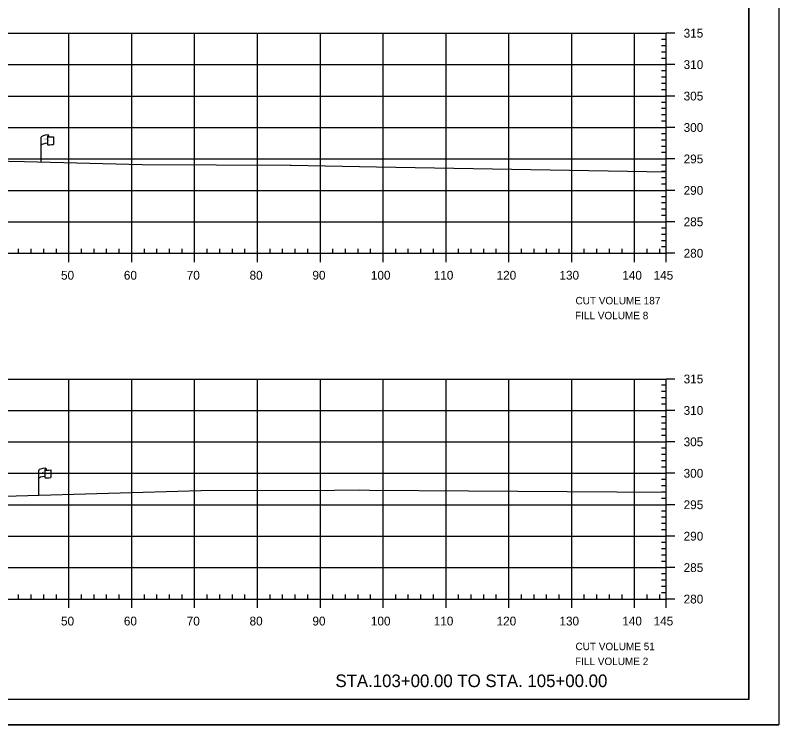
# Model space of a CAD drawing. Extents: x 1370843 to 1371177, y 380307 to 382654.
# Drawn here: x 1371055.2 to 1371176.6, y 380520.8 to 380633.6 of the extents above; entities that cross this region are included whole.
import ezdxf

# ---------------------------------------------------------------- set-up
doc = ezdxf.new("R2010")
doc.units = 0
for name, color, linetype in [('R_Axis', 7, 'Continuous'), ('R_Axis Annot', 7, 'Continuous'), ('R_Border', 7, 'Continuous'), ('R_Border Notes', 7, 'Continuous'), ('R_Draft', 7, 'Continuous'), ('R_Exist Surface', 7, 'Continuous'), ('R_Grid', 7, 'Continuous'), ('R_No Plot', 7, 'Continuous'), ('R_ROW', 7, 'Continuous')]:
    doc.layers.add(name, color=color, linetype=linetype)

msp = doc.modelspace()

# ---------------------------------------------------------------- linework, layer by layer
at = {"layer": 'R_Axis'}
for p, q in [((1371158.71, 380595.79), (1371158.71, 380630.79)), ((1371160.11, 380630.79), (1371158.71, 380630.79)), ((1371158.71, 380629.79), (1371158.01, 380629.79)), ((1371158.71, 380628.79), (1371158.01, 380628.79)), ((1371158.71, 380627.79), (1371158.01, 380627.79)), ((1371158.71, 380626.79), (1371158.01, 380626.79)), ((1371160.11, 380625.79), (1371158.71, 380625.79)), ((1371158.71, 380624.79), (1371158.01, 380624.79)), ((1371158.71, 380623.79), (1371158.01, 380623.79)), ((1371158.71, 380622.79), (1371158.01, 380622.79)), ((1371158.71, 380621.79), (1371158.01, 380621.79)), ((1371160.11, 380620.79), (1371158.71, 380620.79)), ((1371158.71, 380619.79), (1371158.01, 380619.79)), ((1371158.71, 380618.79), (1371158.01, 380618.79)), ((1371158.71, 380617.79), (1371158.01, 380617.79)), ((1371158.71, 380616.79), (1371158.01, 380616.79)), ((1371160.11, 380615.79), (1371158.71, 380615.79)), ((1371158.71, 380614.79), (1371158.01, 380614.79)), ((1371158.71, 380613.79), (1371158.01, 380613.79)), ((1371158.71, 380612.79), (1371158.01, 380612.79)), ((1371158.71, 380611.79), (1371158.01, 380611.79)), ((1371160.11, 380610.79), (1371158.71, 380610.79)), ((1371158.71, 380609.79), (1371158.01, 380609.79)), ((1371158.71, 380608.79), (1371158.01, 380608.79)), ((1371158.71, 380607.79), (1371158.01, 380607.79)), ((1371158.71, 380606.79), (1371158.01, 380606.79)), ((1371160.11, 380605.79), (1371158.71, 380605.79)), ((1371158.71, 380604.79), (1371158.01, 380604.79)), ((1371158.71, 380603.79), (1371158.01, 380603.79)), ((1371158.71, 380602.79), (1371158.01, 380602.79)), ((1371158.71, 380601.79), (1371158.01, 380601.79)), ((1371158.71, 380599.79), (1371158.01, 380599.79)), ((1371160.11, 380600.79), (1371158.71, 380600.79)), ((1371158.71, 380598.79), (1371158.01, 380598.79)), ((1371158.71, 380597.79), (1371158.01, 380597.79)), ((1371055.71, 380595.79), (1371055.71, 380596.49)), ((1371057.71, 380595.79), (1371057.71, 380596.49)), ((1371059.71, 380595.79), (1371059.71, 380596.49)), ((1371061.71, 380595.79), (1371061.71, 380596.49)), ((1371065.71, 380595.79), (1371065.71, 380596.49)), ((1371067.71, 380595.79), (1371067.71, 380596.49)), ((1371069.71, 380595.79), (1371069.71, 380596.49)), ((1371071.71, 380595.79), (1371071.71, 380596.49)), ((1371075.71, 380595.79), (1371075.71, 380596.49)), ((1371077.71, 380595.79), (1371077.71, 380596.49)), ((1371079.71, 380595.79), (1371079.71, 380596.49)), ((1371081.71, 380595.79), (1371081.71, 380596.49)), ((1371085.71, 380595.79), (1371085.71, 380596.49)), ((1371087.71, 380595.79), (1371087.71, 380596.49)), ((1371089.71, 380595.79), (1371089.71, 380596.49)), ((1371091.71, 380595.79), (1371091.71, 380596.49)), ((1371095.71, 380595.79), (1371095.71, 380596.49)), ((1371097.71, 380595.79), (1371097.71, 380596.49)), ((1371099.71, 380595.79), (1371099.71, 380596.49)), ((1371101.71, 380595.79), (1371101.71, 380596.49)), ((1371105.71, 380595.79), (1371105.71, 380596.49)), ((1371107.71, 380595.79), (1371107.71, 380596.49)), ((1371109.71, 380595.79), (1371109.71, 380596.49)), ((1371111.71, 380595.79), (1371111.71, 380596.49)), ((1371115.71, 380595.79), (1371115.71, 380596.49)), ((1371117.71, 380595.79), (1371117.71, 380596.49)), ((1371119.71, 380595.79), (1371119.71, 380596.49)), ((1371121.71, 380595.79), (1371121.71, 380596.49)), ((1371125.71, 380595.79), (1371125.71, 380596.49)), ((1371127.71, 380595.79), (1371127.71, 380596.49)), ((1371129.71, 380595.79), (1371129.71, 380596.49)), ((1371131.71, 380595.79), (1371131.71, 380596.49)), ((1371135.71, 380595.79), (1371135.71, 380596.49)), ((1371137.71, 380595.79), (1371137.71, 380596.49)), ((1371139.71, 380595.79), (1371139.71, 380596.49)), ((1371141.71, 380595.79), (1371141.71, 380596.49)), ((1371145.71, 380595.79), (1371145.71, 380596.49)), ((1371147.71, 380595.79), (1371147.71, 380596.49)), ((1371149.71, 380595.79), (1371149.71, 380596.49)), ((1371151.71, 380595.79), (1371151.71, 380596.49)), ((1371155.71, 380595.79), (1371155.71, 380596.49)), ((1371157.71, 380595.79), (1371157.71, 380596.49)), ((1371158.71, 380596.79), (1371158.01, 380596.79)), ((1370868.71, 380595.79), (1371158.71, 380595.79)), ((1371063.71, 380594.39), (1371063.71, 380595.79)), ((1371073.71, 380594.39), (1371073.71, 380595.79)), ((1371083.71, 380594.39), (1371083.71, 380595.79)), ((1371093.71, 380594.39), (1371093.71, 380595.79)), ((1371103.71, 380594.39), (1371103.71, 380595.79)), ((1371113.71, 380594.39), (1371113.71, 380595.79)), ((1371123.71, 380594.39), (1371123.71, 380595.79)), ((1371133.71, 380594.39), (1371133.71, 380595.79)), ((1371143.71, 380594.39), (1371143.71, 380595.79)), ((1371153.71, 380594.39), (1371153.71, 380595.79)), ((1371158.71, 380594.39), (1371158.71, 380595.79)), ((1371160.11, 380595.79), (1371158.71, 380595.79)), ((1371158.71, 380540.79), (1371158.71, 380575.79)), ((1371160.11, 380575.79), (1371158.71, 380575.79)), ((1371158.71, 380574.79), (1371158.01, 380574.79)), ((1371158.71, 380573.79), (1371158.01, 380573.79)), ((1371158.71, 380572.79), (1371158.01, 380572.79)), ((1371158.71, 380571.79), (1371158.01, 380571.79)), ((1371160.11, 380570.79), (1371158.71, 380570.79)), ((1371158.71, 380569.79), (1371158.01, 380569.79)), ((1371158.71, 380568.79), (1371158.01, 380568.79)), ((1371158.71, 380567.79), (1371158.01, 380567.79)), ((1371158.71, 380566.79), (1371158.01, 380566.79)), ((1371160.11, 380565.79), (1371158.71, 380565.79)), ((1371158.71, 380564.79), (1371158.01, 380564.79)), ((1371158.71, 380563.79), (1371158.01, 380563.79)), ((1371158.71, 380562.79), (1371158.01, 380562.79)), ((1371158.71, 380561.79), (1371158.01, 380561.79)), ((1371158.71, 380559.79), (1371158.01, 380559.79)), ((1371160.11, 380560.79), (1371158.71, 380560.79)), ((1371158.71, 380558.79), (1371158.01, 380558.79)), ((1371158.71, 380557.79), (1371158.01, 380557.79)), ((1371158.71, 380556.79), (1371158.01, 380556.79)), ((1371158.71, 380554.79), (1371158.01, 380554.79)), ((1371160.11, 380555.79), (1371158.71, 380555.79)), ((1371158.71, 380553.79), (1371158.01, 380553.79)), ((1371158.71, 380552.79), (1371158.01, 380552.79)), ((1371158.71, 380551.79), (1371158.01, 380551.79)), ((1371160.11, 380550.79), (1371158.71, 380550.79)), ((1371158.71, 380549.79), (1371158.01, 380549.79)), ((1371158.71, 380548.79), (1371158.01, 380548.79)), ((1371158.71, 380547.79), (1371158.01, 380547.79)), ((1371158.71, 380546.79), (1371158.01, 380546.79)), ((1371160.11, 380545.79), (1371158.71, 380545.79)), ((1371158.71, 380544.79), (1371158.01, 380544.79)), ((1371158.71, 380543.79), (1371158.01, 380543.79)), ((1371158.71, 380542.79), (1371158.01, 380542.79)), ((1371055.71, 380540.79), (1371055.71, 380541.49)), ((1371057.71, 380540.79), (1371057.71, 380541.49)), ((1371059.71, 380540.79), (1371059.71, 380541.49)), ((1371061.71, 380540.79), (1371061.71, 380541.49)), ((1371065.71, 380540.79), (1371065.71, 380541.49)), ((1371067.71, 380540.79), (1371067.71, 380541.49)), ((1371069.71, 380540.79), (1371069.71, 380541.49)), ((1371071.71, 380540.79), (1371071.71, 380541.49)), ((1371075.71, 380540.79), (1371075.71, 380541.49)), ((1371077.71, 380540.79), (1371077.71, 380541.49)), ((1371079.71, 380540.79), (1371079.71, 380541.49)), ((1371081.71, 380540.79), (1371081.71, 380541.49)), ((1371085.71, 380540.79), (1371085.71, 380541.49)), ((1371087.71, 380540.79), (1371087.71, 380541.49)), ((1371089.71, 380540.79), (1371089.71, 380541.49)), ((1371091.71, 380540.79), (1371091.71, 380541.49)), ((1371095.71, 380540.79), (1371095.71, 380541.49)), ((1371097.71, 380540.79), (1371097.71, 380541.49)), ((1371099.71, 380540.79), (1371099.71, 380541.49)), ((1371101.71, 380540.79), (1371101.71, 380541.49)), ((1371105.71, 380540.79), (1371105.71, 380541.49)), ((1371107.71, 380540.79), (1371107.71, 380541.49)), ((1371109.71, 380540.79), (1371109.71, 380541.49)), ((1371111.71, 380540.79), (1371111.71, 380541.49)), ((1371115.71, 380540.79), (1371115.71, 380541.49)), ((1371117.71, 380540.79), (1371117.71, 380541.49)), ((1371119.71, 380540.79), (1371119.71, 380541.49)), ((1371121.71, 380540.79), (1371121.71, 380541.49)), ((1371125.71, 380540.79), (1371125.71, 380541.49)), ((1371127.71, 380540.79), (1371127.71, 380541.49)), ((1371129.71, 380540.79), (1371129.71, 380541.49)), ((1371131.71, 380540.79), (1371131.71, 380541.49)), ((1371135.71, 380540.79), (1371135.71, 380541.49)), ((1371137.71, 380540.79), (1371137.71, 380541.49)), ((1371139.71, 380540.79), (1371139.71, 380541.49)), ((1371141.71, 380540.79), (1371141.71, 380541.49)), ((1371145.71, 380540.79), (1371145.71, 380541.49)), ((1371147.71, 380540.79), (1371147.71, 380541.49)), ((1371149.71, 380540.79), (1371149.71, 380541.49)), ((1371151.71, 380540.79), (1371151.71, 380541.49)), ((1371155.71, 380540.79), (1371155.71, 380541.49)), ((1371157.71, 380540.79), (1371157.71, 380541.49)), ((1371158.71, 380541.79), (1371158.01, 380541.79)), ((1370868.71, 380540.79), (1371158.71, 380540.79)), ((1371063.71, 380539.39), (1371063.71, 380540.79)), ((1371073.71, 380539.39), (1371073.71, 380540.79)), ((1371083.71, 380539.39), (1371083.71, 380540.79)), ((1371093.71, 380539.39), (1371093.71, 380540.79)), ((1371103.71, 380539.39), (1371103.71, 380540.79)), ((1371113.71, 380539.39), (1371113.71, 380540.79)), ((1371123.71, 380539.39), (1371123.71, 380540.79)), ((1371133.71, 380539.39), (1371133.71, 380540.79)), ((1371143.71, 380539.39), (1371143.71, 380540.79)), ((1371153.71, 380539.39), (1371153.71, 380540.79)), ((1371158.71, 380539.39), (1371158.71, 380540.79)), ((1371160.11, 380540.79), (1371158.71, 380540.79))]:
    msp.add_line(p, q, dxfattribs=at)
at = {"layer": 'R_Border'}
for q in [(1371171.89, 380730.25), (1370855.71, 380524.79)]:
    msp.add_line((1371171.89, 380524.79), q, dxfattribs=at)
at = {"layer": 'R_Exist Surface'}
for p, q in [((1371112.65, 380609.55), (1371158.71, 380608.73)), ((1371111.52, 380558.11), (1371158.71, 380557.77))]:
    msp.add_line(p, q, dxfattribs=at)
for points in [[(1371049.16, 380610.54), (1371056.65, 380610.39), (1371075.37, 380609.93), (1371098.9, 380609.79), (1371099.01, 380609.79), (1371099.07, 380609.79), (1371112.65, 380609.55)], [(1371050.64, 380557.1), (1371055.31, 380557.23), (1371084.71, 380558.06), (1371105.98, 380558.11), (1371109.98, 380558.15), (1371111.52, 380558.11)]]:
    msp.add_lwpolyline(points, dxfattribs=at)
at = {"layer": 'R_Grid'}
for p, q in [((1370868.71, 380630.79), (1371158.71, 380630.79)), ((1371063.71, 380595.79), (1371063.71, 380630.79)), ((1371073.71, 380595.79), (1371073.71, 380630.79)), ((1371083.71, 380595.79), (1371083.71, 380630.79)), ((1371093.71, 380595.79), (1371093.71, 380630.79)), ((1371103.71, 380595.79), (1371103.71, 380630.79)), ((1371113.71, 380595.79), (1371113.71, 380630.79)), ((1371123.71, 380595.79), (1371123.71, 380630.79)), ((1371133.71, 380595.79), (1371133.71, 380630.79)), ((1371143.71, 380595.79), (1371143.71, 380630.79)), ((1371153.71, 380595.79), (1371153.71, 380630.79)), ((1371158.71, 380595.79), (1371158.71, 380630.79)), ((1370868.71, 380625.79), (1371158.71, 380625.79)), ((1370868.71, 380620.79), (1371158.71, 380620.79)), ((1370868.71, 380615.79), (1371158.71, 380615.79)), ((1370868.71, 380610.79), (1371158.71, 380610.79)), ((1370868.71, 380605.79), (1371158.71, 380605.79)), ((1370868.71, 380600.79), (1371158.71, 380600.79)), ((1370868.71, 380595.79), (1371158.71, 380595.79)), ((1370868.71, 380575.79), (1371158.71, 380575.79)), ((1371063.71, 380540.79), (1371063.71, 380575.79)), ((1371073.71, 380540.79), (1371073.71, 380575.79)), ((1371083.71, 380540.79), (1371083.71, 380575.79)), ((1371093.71, 380540.79), (1371093.71, 380575.79)), ((1371103.71, 380540.79), (1371103.71, 380575.79)), ((1371113.71, 380540.79), (1371113.71, 380575.79)), ((1371123.71, 380540.79), (1371123.71, 380575.79)), ((1371133.71, 380540.79), (1371133.71, 380575.79)), ((1371143.71, 380540.79), (1371143.71, 380575.79)), ((1371153.71, 380540.79), (1371153.71, 380575.79)), ((1371158.71, 380540.79), (1371158.71, 380575.79)), ((1370868.71, 380570.79), (1371158.71, 380570.79)), ((1370868.71, 380565.79), (1371158.71, 380565.79)), ((1370868.71, 380560.79), (1371158.71, 380560.79)), ((1370868.71, 380555.79), (1371158.71, 380555.79)), ((1370868.71, 380550.79), (1371158.71, 380550.79)), ((1370868.71, 380545.79), (1371158.71, 380545.79)), ((1370868.71, 380540.79), (1371158.71, 380540.79))]:
    msp.add_line(p, q, dxfattribs=at)
at = {"layer": 'R_No Plot'}
msp.add_line((1370843.31, 380520.81), (1371176.64, 380520.81), dxfattribs=at)
for points in [[(1370843.3, 380734.14), (1371176.64, 380734.14), (1371176.64, 380520.8), (1370843.3, 380520.8)], [(1371089.63, 380730.25), (1371089.63, 380720.37), (1371125.36, 380720.37), (1371125.36, 380717.45), (1371148.56, 380717.45), (1371148.56, 380693.11), (1371171.89, 380693.11), (1371171.89, 380524.79), (1370855.71, 380524.79), (1370855.71, 380730.25)]]:
    msp.add_lwpolyline(points, close=True, dxfattribs=at)
at = {"layer": 'R_ROW'}
for p, q in [((1371059.31, 380610.32), (1371059.31, 380614.28)), ((1371060.3, 380614.37), (1371060.3, 380614.36)), ((1371060.3, 380614.36), (1371060.3, 380613.13)), ((1371060.47, 380614.53), (1371060.47, 380614.29)), ((1371061.24, 380614.33), (1371061.24, 380613.09)), ((1371058.91, 380557.33), (1371058.91, 380561.28)), ((1371059.9, 380561.37), (1371059.9, 380561.36)), ((1371059.9, 380561.36), (1371059.9, 380560.13)), ((1371060.07, 380561.53), (1371060.07, 380561.29)), ((1371060.84, 380561.34), (1371060.84, 380560.1))]:
    msp.add_line(p, q, dxfattribs=at)
for centre, radius, start, end in [((1371060.38, 380614.37), 0.078, 88.6458, 274.2828), ((1371060.39, 380614.53), 0.0783, 263.0712, 93.9564), ((1371060.38, 380613.13), 0.0783, 180, 273.9564), ((1371059.98, 380561.38), 0.078, 88.6458, 274.2828), ((1371059.99, 380561.53), 0.0783, 263.0712, 93.9564), ((1371059.98, 380560.13), 0.0783, 180, 273.9564)]:
    msp.add_arc(centre, radius, start, end, dxfattribs=at)
for centre, major_axis, ratio, start_param, end_param in [((1371060.89, 380614.32), (-1.58, -0.04), 0.19887, 5.030368, 6.283185), ((1371061.59, 380614.43), (-1.23, -0.13), 0.052933, 0.159456, 1.268315), ((1371060.88, 380613), (-1.58, -0.04), 0.19887, 5.083035, 6.194897), ((1371061.59, 380613.19), (-1.23, -0.13), 0.052933, 0.159456, 1.268315), ((1371060.49, 380561.32), (-1.58, -0.04), 0.19887, 5.030368, 6.283185), ((1371061.2, 380561.44), (-1.23, -0.13), 0.052933, 0.159456, 1.268315), ((1371060.48, 380560.01), (-1.58, -0.04), 0.19887, 5.083035, 6.194897), ((1371061.2, 380560.2), (-1.23, -0.13), 0.052933, 0.159456, 1.268315)]:
    msp.add_ellipse(centre, major_axis=major_axis, ratio=ratio, start_param=start_param, end_param=end_param, dxfattribs=at)

# ---------------------------------------------------------------- texts
at = {"layer": 'R_Axis Annot'}
for s, p in [('315', (1371161.51, 380630.09)), ('310', (1371161.51, 380625.09)), ('305', (1371161.51, 380620.09)), ('300', (1371161.51, 380615.09)), ('295', (1371161.51, 380610.09)), ('290', (1371161.51, 380605.09)), ('285', (1371161.51, 380600.09)), ('280', (1371161.51, 380595.09)), ('50', (1371062.45, 380591.59)), ('60', (1371072.45, 380591.59)), ('70', (1371082.45, 380591.59)), ('80', (1371092.45, 380591.59)), ('90', (1371102.45, 380591.59)), ('100', (1371111.75, 380591.59)), ('110', (1371121.75, 380591.59)), ('120', (1371131.75, 380591.59)), ('130', (1371141.75, 380591.59)), ('140', (1371151.75, 380591.59)), ('145', (1371156.73, 380591.59)), ('315', (1371161.51, 380575.09)), ('310', (1371161.51, 380570.09)), ('305', (1371161.51, 380565.09)), ('300', (1371161.51, 380560.09)), ('295', (1371161.51, 380555.09)), ('290', (1371161.51, 380550.09)), ('285', (1371161.51, 380545.09)), ('280', (1371161.51, 380540.09)), ('50', (1371062.45, 380536.59)), ('60', (1371072.45, 380536.59)), ('70', (1371082.45, 380536.59)), ('80', (1371092.45, 380536.59)), ('90', (1371102.45, 380536.59)), ('100', (1371111.75, 380536.59)), ('110', (1371121.75, 380536.59)), ('120', (1371131.75, 380536.59)), ('130', (1371141.75, 380536.59)), ('140', (1371151.75, 380536.59)), ('145', (1371156.73, 380536.59))]:
    msp.add_text(s, height=1.4, dxfattribs=at).set_placement(p)
at = {"layer": 'R_Border Notes'}
for s, p in [('CUT VOLUME 187', (1371144.31, 380587.66)), ('FILL VOLUME 8', (1371144.24, 380585.29)), ('CUT VOLUME 51', (1371144.31, 380532.66)), ('FILL VOLUME 2', (1371144.24, 380530.29))]:
    msp.add_text(s, height=1.1875, dxfattribs=at).set_placement(p)
at = {"layer": 'R_Draft'}
msp.add_text('STA.103+00.00 TO STA. 105+00.00', height=2, dxfattribs=at).set_placement((1371106.11, 380526.79))
at = {"layer": 'R_ROW'}
for s, height, rotation, p in [('DWB 11-9-07', 0.001, 90, (1371060.47, 380614.29)), ('R ', 0.2, 9.9884, (1371059.82, 380613.78)), (' O', 0.2, 9.9884, (1371059.97, 380613.82)), ('W', 0.2, 351.1788, (1371060.3, 380613.65)), ('DWB 11-9-07', 0.001, 5.0717, (1371061.23, 380613.09)), ('DWB 11-9-07', 0.001, 90, (1371059.3, 380610.33)), ('R ', 0.2, 9.9884, (1371059.43, 380560.78)), (' O', 0.2, 9.9884, (1371059.57, 380560.83)), ('W', 0.2, 351.1788, (1371059.9, 380560.66)), ('DWB 11-9-07', 0.001, 90, (1371060.07, 380561.29)), ('DWB 11-9-07', 0.001, 5.0717, (1371060.83, 380560.1)), ('DWB 11-9-07', 0.001, 90, (1371058.91, 380557.33))]:
    msp.add_text(s, height=height, rotation=rotation, dxfattribs=at).set_placement(p)

doc.saveas('drawing.dxf')
